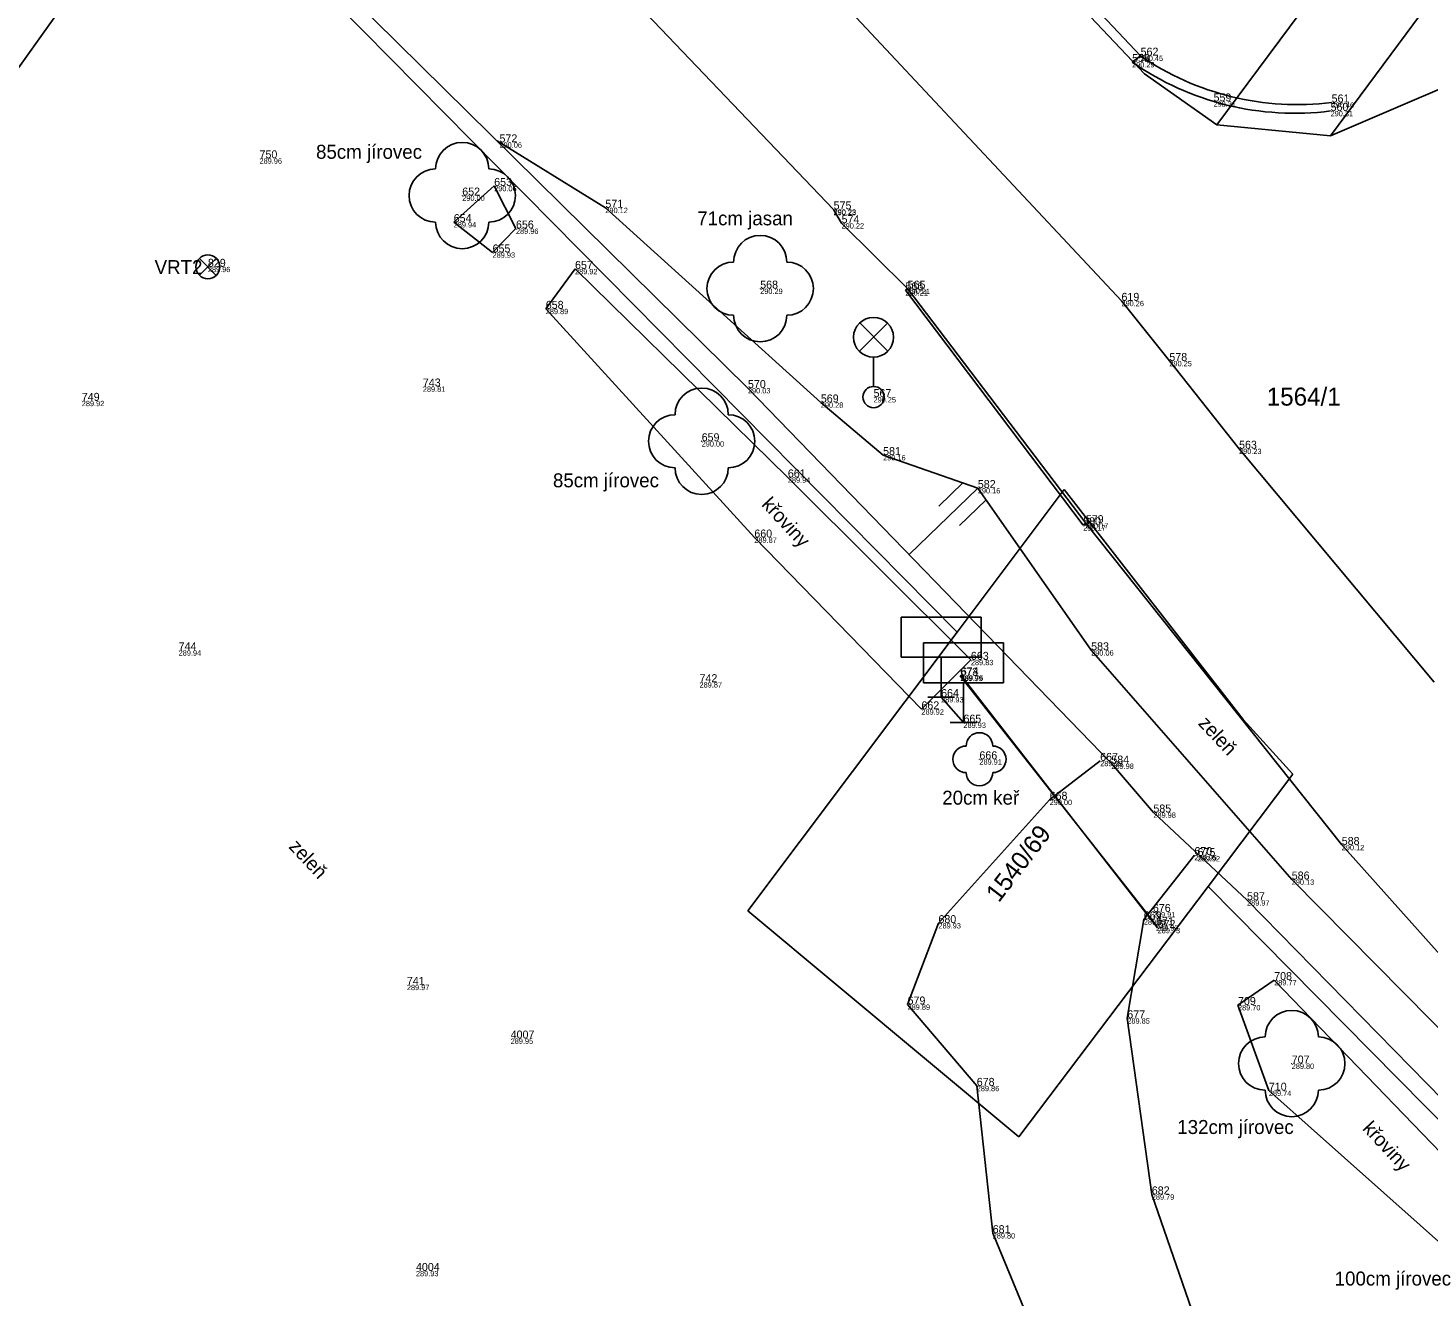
# Model space of a CAD drawing. Extents: x -805057 to -804930, y -994399 to -994240.
# Drawn here: x -805005.92 to -804979.61, y -994307.89 to -994284.05 of the extents above; entities that cross this region are included whole.
import ezdxf

# ---------------------------------------------------------------- set-up
doc = ezdxf.new("R2010")
doc.units = 0
for name, color, linetype in [('bod cislo', 7, 'Continuous'), ('bod pozice', 7, 'Continuous'), ('bod výška', 7, 'Continuous'), ('Katastralni mapa', 7, 'Continuous'), ('komunikace', 7, 'Continuous'), ('lampa', 7, 'Continuous'), ('plot', 7, 'Continuous'), ('podlaha', 7, 'Continuous'), ('popis', 7, 'Continuous'), ('strom', 7, 'Continuous'), ('svah', 7, 'Continuous'), ('trubka', 7, 'Continuous'), ('značka', 7, 'Continuous'), ('šrafy', 7, 'Continuous')]:
    doc.layers.add(name, color=color, linetype=linetype)

msp = doc.modelspace()

# ---------------------------------------------------------------- linework, layer by layer
at = {"layer": 'bod pozice'}
for p, q in [((-804985.01, -994284.57), (-804985.01, -994284.57)), ((-804985.17, -994284.69), (-804985.17, -994284.69)), ((-804983.64, -994285.43), (-804983.64, -994285.43)), ((-804981.44, -994285.61), (-804981.44, -994285.61)), ((-804981.42, -994285.45), (-804981.42, -994285.45)), ((-804997.06, -994286.2), (-804997.06, -994286.2)), ((-805001.57, -994286.5), (-805001.57, -994286.5)), ((-804997.76, -994287.2), (-804997.76, -994287.2)), ((-804997.16, -994287.02), (-804997.16, -994287.02)), ((-804995.07, -994287.43), (-804995.07, -994287.43)), ((-804990.78, -994287.46), (-804990.78, -994287.46)), ((-804997.92, -994287.7), (-804997.92, -994287.7)), ((-804990.63, -994287.72), (-804990.63, -994287.72)), ((-804996.75, -994287.82), (-804996.75, -994287.82)), ((-804997.19, -994288.27), (-804997.19, -994288.27)), ((-805002.54, -994288.54), (-805002.54, -994288.54)), ((-804995.64, -994288.58), (-804995.64, -994288.58)), ((-804992.16, -994288.95), (-804992.16, -994288.95)), ((-804989.43, -994288.98), (-804989.43, -994288.98)), ((-804989.39, -994288.95), (-804989.39, -994288.95)), ((-804985.37, -994289.18), (-804985.37, -994289.18)), ((-804996.19, -994289.33), (-804996.19, -994289.33)), ((-804984.47, -994290.31), (-804984.47, -994290.31)), ((-804998.5, -994290.79), (-804998.5, -994290.79)), ((-804992.39, -994290.82), (-804992.39, -994290.82)), ((-805004.91, -994291.06), (-805004.91, -994291.06)), ((-804991.02, -994291.09), (-804991.02, -994291.09)), ((-804990.03, -994290.99), (-804990.03, -994290.99)), ((-804993.26, -994291.82), (-804993.26, -994291.82)), ((-804989.85, -994292.08), (-804989.85, -994292.08)), ((-804983.16, -994291.96), (-804983.16, -994291.96)), ((-804991.64, -994292.5), (-804991.64, -994292.5)), ((-804988.07, -994292.7), (-804988.07, -994292.7)), ((-804986.09, -994293.4), (-804986.09, -994293.4)), ((-804986.04, -994293.36), (-804986.04, -994293.36)), ((-804992.27, -994293.63), (-804992.27, -994293.63)), ((-805003.09, -994295.75), (-805003.09, -994295.75)), ((-804985.94, -994295.75), (-804985.94, -994295.75)), ((-804988.2, -994295.93), (-804988.2, -994295.93)), ((-804993.3, -994296.35), (-804993.3, -994296.35)), ((-804988.4, -994296.23), (-804988.4, -994296.23)), ((-804988.39, -994296.22), (-804988.39, -994296.22)), ((-804988.76, -994296.63), (-804988.76, -994296.63)), ((-804989.13, -994296.86), (-804989.13, -994296.86)), ((-804988.34, -994297.11), (-804988.34, -994297.11)), ((-804988.04, -994297.8), (-804988.04, -994297.8)), ((-804985.77, -994297.83), (-804985.77, -994297.83)), ((-804985.56, -994297.88), (-804985.56, -994297.88)), ((-804986.72, -994298.56), (-804986.72, -994298.56)), ((-804984.77, -994298.8), (-804984.77, -994298.8)), ((-804981.23, -994299.41), (-804981.23, -994299.41)), ((-804984, -994299.6), (-804984, -994299.6)), ((-804983.94, -994299.62), (-804983.94, -994299.62)), ((-804982.17, -994300.06), (-804982.17, -994300.06)), ((-804983.01, -994300.45), (-804983.01, -994300.45)), ((-804988.81, -994300.88), (-804988.81, -994300.88)), ((-804984.95, -994300.81), (-804984.95, -994300.81)), ((-804984.78, -994300.67), (-804984.78, -994300.67)), ((-804984.72, -994300.92), (-804984.72, -994300.92)), ((-804984.69, -994300.97), (-804984.69, -994300.97)), ((-804982.5, -994301.95), (-804982.5, -994301.95)), ((-804998.8, -994302.04), (-804998.8, -994302.04)), ((-804989.39, -994302.41), (-804989.39, -994302.41)), ((-804983.18, -994302.42), (-804983.18, -994302.42)), ((-804985.26, -994302.67), (-804985.26, -994302.67)), ((-804996.85, -994303.05), (-804996.85, -994303.05)), ((-804982.17, -994303.52), (-804982.17, -994303.52)), ((-804988.09, -994303.94), (-804988.09, -994303.94)), ((-804982.6, -994304.03), (-804982.6, -994304.03)), ((-804984.8, -994305.98), (-804984.8, -994305.98)), ((-804987.79, -994306.71), (-804987.79, -994306.71)), ((-804998.63, -994307.42), (-804998.63, -994307.42))]:
    msp.add_line(p, q, dxfattribs=at)
at = {"layer": 'Katastralni mapa'}
for points in [[(-804981.44, -994286.08), (-804950.9, -994244.881)], [(-804963.36, -994258.68), (-804983.58, -994285.87)], [(-805017.39, -994266.11), (-804988.46, -994295.41)], [(-804989.57, -994280.01), (-804984.94, -994284.91), (-804983.58, -994285.87)], [(-804981.44, -994286.08), (-804977.99, -994284.6), (-804975.09, -994288.91)], [(-804983.58, -994285.87), (-804981.44, -994286.08)], [(-804986.45, -994292.73), (-804988.46, -994295.41)], [(-804986.45, -994292.73), (-804983.08, -994297.05), (-804982.15, -994298.08)], [(-804988.46, -994295.41), (-804992.39, -994300.65)], [(-804982.15, -994298.08), (-804983.74, -994300.19)], [(-804983.74, -994300.19), (-804987.3, -994304.9)], [(-804953.13, -994331.19), (-804983.74, -994300.19)], [(-804992.39, -994300.65), (-804987.3, -994304.9)]]:
    msp.add_lwpolyline(points, dxfattribs=at)
at = {"layer": 'komunikace'}
for p, q in [((-804985.37, -994289.18), (-805005.75, -994267.39)), ((-804989.14, -994280.19), (-804985.01, -994284.57)), ((-804985.01, -994284.57), (-804985.17, -994284.69)), ((-804989.39, -994288.95), (-804990.63, -994287.72)), ((-804989.39, -994288.95), (-804989.43, -994288.98)), ((-804986.09, -994293.4), (-804989.43, -994288.98)), ((-804986.04, -994293.36), (-804989.39, -994288.95)), ((-804984.47, -994290.31), (-804985.37, -994289.18)), ((-804983.16, -994291.96), (-804984.47, -994290.31)), ((-804979.49, -994296.35), (-804983.16, -994291.96)), ((-804986.04, -994293.36), (-804986.09, -994293.4)), ((-804981.23, -994299.41), (-804986.04, -994293.36)), ((-804986.72, -994298.56), (-804985.77, -994297.83)), ((-804988.81, -994300.88), (-804986.72, -994298.56)), ((-804974.7, -994306.71), (-804981.23, -994299.41)), ((-804984.95, -994300.81), (-804984, -994299.6)), ((-804989.39, -994302.41), (-804988.81, -994300.88)), ((-804984.95, -994300.81), (-804985.26, -994302.67)), ((-804988.09, -994303.94), (-804989.39, -994302.41)), ((-804985.26, -994302.67), (-804984.8, -994305.98)), ((-804987.79, -994306.71), (-804988.09, -994303.94)), ((-804980.44, -994318.62), (-804984.8, -994305.98)), ((-804987.79, -994306.71), (-804983.08, -994318.08))]:
    msp.add_line(p, q, dxfattribs=at)
msp.add_lwpolyline([(-804990.63, -994287.72), (-804990.78, -994287.46), (-804995.24, -994282.79)], dxfattribs=at)
for centre, major_axis, ratio, start_param, end_param in [((-804982.063, -994280.277), (1.576, -4.969), 0.99965, 5.374004, 6.10027), ((-804982.115, -994280.33), (5.308, -0.434), 0.999468, 4.183086, 4.921153)]:
    msp.add_ellipse(centre, major_axis=major_axis, ratio=ratio, start_param=start_param, end_param=end_param, dxfattribs=at)
at = {"layer": 'lampa'}
for p, q in [((-804990.294, -994290.128), (-804989.766, -994289.6)), ((-804990.294, -994290.128), (-804989.766, -994289.6)), ((-804989.758, -994290.125), (-804990.286, -994289.596)), ((-804989.758, -994290.125), (-804990.286, -994289.596)), ((-804990.03, -994290.79), (-804990.03, -994290.24)), ((-804990.03, -994290.79), (-804990.03, -994290.24))]:
    msp.add_line(p, q, dxfattribs=at)
for centre, radius in [((-804990.03, -994289.865), 0.375), ((-804990.03, -994289.865), 0.375), ((-804990.03, -994290.99), 0.2), ((-804990.03, -994290.99), 0.2)]:
    msp.add_circle(centre, radius, dxfattribs=at)
at = {"layer": 'plot'}
for p, q in [((-805002.96, -994280.4), (-805015.07, -994297.35)), ((-804992.39, -994290.82), (-805002.96, -994280.4)), ((-804985.56, -994297.88), (-804992.39, -994290.82)), ((-804985.56, -994297.88), (-804984.77, -994298.8)), ((-804983.01, -994300.45), (-804984.77, -994298.8)), ((-804972.34, -994311.34), (-804983.01, -994300.45))]:
    msp.add_line(p, q, dxfattribs=at)
at = {"layer": 'podlaha'}
for p, q in [((-805002.699, -994288.698), (-805002.382, -994288.382)), ((-805002.382, -994288.701), (-805002.699, -994288.382))]:
    msp.add_line(p, q, dxfattribs=at)
msp.add_circle((-805002.54, -994288.54), 0.225, dxfattribs=at)
at = {"layer": 'strom'}
for p, q in [((-804997.92, -994287.7), (-804997.16, -994287.02)), ((-804996.75, -994287.82), (-804997.16, -994287.02)), ((-804997.19, -994288.27), (-804997.92, -994287.7)), ((-804997.19, -994288.27), (-804996.75, -994287.82)), ((-804995.64, -994288.58), (-804996.19, -994289.33)), ((-804991.64, -994292.5), (-804995.64, -994288.58)), ((-804996.19, -994289.33), (-804992.27, -994293.63)), ((-804988.2, -994295.93), (-804991.64, -994292.5)), ((-804992.27, -994293.63), (-804989.13, -994296.86)), ((-804989.13, -994296.86), (-804988.2, -994295.93)), ((-804983.18, -994302.42), (-804982.5, -994301.95)), ((-804982.5, -994301.95), (-804978.12, -994306.5)), ((-804982.6, -994304.03), (-804983.18, -994302.42)), ((-804978.94, -994307.29), (-804982.6, -994304.03))]:
    msp.add_line(p, q, dxfattribs=at)
for centre, radius in [((-804997.76, -994287.2), 0.0005), ((-804992.16, -994288.95), 0.0005), ((-804993.26, -994291.82), 0.0005), ((-804988.04, -994297.8), 0.00025), ((-804982.17, -994303.52), 0.0005)]:
    msp.add_circle(centre, radius, dxfattribs=at)
for centre, radius, start, end in [((-804997.76, -994286.7), 0.5, 0, 180), ((-804998.26, -994287.2), 0.5, 90, 270), ((-804997.26, -994287.2), 0.5, 270, 90), ((-804997.76, -994287.7), 0.5, 180, 360), ((-804992.16, -994288.45), 0.5, 0, 180), ((-804992.66, -994288.95), 0.5, 90, 270), ((-804991.66, -994288.95), 0.5, 270, 90), ((-804992.16, -994289.45), 0.5, 180, 360), ((-804993.26, -994291.32), 0.5, 0, 180), ((-804993.76, -994291.82), 0.5, 90, 270), ((-804992.76, -994291.82), 0.5, 270, 90), ((-804993.26, -994292.32), 0.5, 180, 360), ((-804988.04, -994297.55), 0.25, 0, 180), ((-804988.29, -994297.8), 0.25, 90, 270), ((-804987.79, -994297.8), 0.25, 270, 90), ((-804988.04, -994298.05), 0.25, 180, 360), ((-804982.17, -994303.02), 0.5, 0, 180), ((-804982.67, -994303.52), 0.5, 90, 270), ((-804981.67, -994303.52), 0.5, 270, 90), ((-804982.17, -994304.02), 0.5, 180, 360)]:
    msp.add_arc(centre, radius, start, end, dxfattribs=at)
at = {"layer": 'svah'}
for p, q in [((-804995.07, -994287.43), (-804997.104, -994286.173)), ((-804991.02, -994291.09), (-804995.07, -994287.43)), ((-804989.85, -994292.08), (-804991.02, -994291.09)), ((-804988.07, -994292.7), (-804989.85, -994292.08)), ((-804985.94, -994295.75), (-804988.07, -994292.7)), ((-804982.17, -994300.06), (-804985.94, -994295.75)), ((-804971.58, -994310.78), (-804982.17, -994300.06))]:
    msp.add_line(p, q, dxfattribs=at)
at = {"layer": 'trubka'}
for p, q in [((-804988.4, -994296.23), (-804988.39, -994296.22)), ((-804984.72, -994300.92), (-804988.4, -994296.23)), ((-804988.39, -994296.22), (-804984.69, -994300.97)), ((-804984.69, -994300.97), (-804984.72, -994300.92))]:
    msp.add_line(p, q, dxfattribs=at)
at = {"layer": 'značka'}
for p, q in [((-804988.76, -994295.88), (-804988.76, -994296.63)), ((-804988.34, -994296.36), (-804988.34, -994297.11)), ((-804989.01, -994296.63), (-804988.51, -994296.63)), ((-804988.34, -994297.11), (-804988.76, -994296.63)), ((-804988.59, -994297.11), (-804988.09, -994297.11))]:
    msp.add_line(p, q, dxfattribs=at)
for points in [[(-804989.51, -994295.88), (-804988.01, -994295.88), (-804988.01, -994295.13), (-804989.51, -994295.13)], [(-804989.09, -994296.36), (-804987.59, -994296.36), (-804987.59, -994295.61), (-804989.09, -994295.61)]]:
    msp.add_lwpolyline(points, close=True, dxfattribs=at)
at = {"layer": 'šrafy'}
for p, q in [((-804988.07, -994292.7), (-804989.36, -994293.952)), ((-804988.351, -994292.602), (-804988.802, -994293.039)), ((-804987.915, -994292.922), (-804988.413, -994293.405))]:
    msp.add_line(p, q, dxfattribs=at)

# ---------------------------------------------------------------- texts
at = {"layer": 'bod cislo'}
for s, p in [('558    ', (-804985.17, -994284.69)), ('562    ', (-804985.01, -994284.57)), ('559    ', (-804983.64, -994285.43)), ('561    ', (-804981.42, -994285.45)), ('560    ', (-804981.44, -994285.61)), ('572    ', (-804997.06, -994286.2)), ('750    ', (-805001.57, -994286.5)), ('653    ', (-804997.16, -994287.02)), ('652    ', (-804997.76, -994287.2)), ('571    ', (-804995.07, -994287.43)), ('575    ', (-804990.78, -994287.46)), ('654    ', (-804997.92, -994287.7)), ('656    ', (-804996.75, -994287.82)), ('574    ', (-804990.63, -994287.72)), ('655    ', (-804997.19, -994288.27)), ('829    ', (-805002.54, -994288.54)), ('657    ', (-804995.64, -994288.58)), ('568    ', (-804992.16, -994288.95)), ('566    ', (-804989.43, -994288.98)), ('565    ', (-804989.39, -994288.95)), ('619    ', (-804985.37, -994289.18)), ('658    ', (-804996.19, -994289.33)), ('578    ', (-804984.47, -994290.31)), ('743    ', (-804998.5, -994290.79)), ('570    ', (-804992.39, -994290.82)), ('567    ', (-804990.03, -994290.99)), ('749    ', (-805004.91, -994291.06)), ('569    ', (-804991.02, -994291.09)), ('659    ', (-804993.26, -994291.82)), ('581    ', (-804989.85, -994292.08)), ('563    ', (-804983.16, -994291.96)), ('661    ', (-804991.64, -994292.5)), ('582    ', (-804988.07, -994292.7)), ('580    ', (-804986.09, -994293.4)), ('579    ', (-804986.04, -994293.36)), ('660    ', (-804992.27, -994293.63)), ('744    ', (-805003.09, -994295.75)), ('583    ', (-804985.94, -994295.75)), ('663    ', (-804988.2, -994295.93)), ('673    ', (-804988.4, -994296.23)), ('674    ', (-804988.39, -994296.22)), ('742    ', (-804993.3, -994296.35)), ('664    ', (-804988.76, -994296.63)), ('662    ', (-804989.13, -994296.86)), ('665    ', (-804988.34, -994297.11)), ('666    ', (-804988.04, -994297.8)), ('667    ', (-804985.77, -994297.83)), ('584    ', (-804985.56, -994297.88)), ('668    ', (-804986.72, -994298.56)), ('585    ', (-804984.77, -994298.8)), ('588    ', (-804981.23, -994299.41)), ('670    ', (-804984, -994299.6)), ('675    ', (-804983.94, -994299.62)), ('586    ', (-804982.17, -994300.06)), ('587    ', (-804983.01, -994300.45)), ('676    ', (-804984.78, -994300.67)), ('680    ', (-804988.81, -994300.88)), ('669    ', (-804984.95, -994300.81)), ('671    ', (-804984.72, -994300.92)), ('672    ', (-804984.69, -994300.97)), ('741    ', (-804998.8, -994302.04)), ('708    ', (-804982.5, -994301.95)), ('679    ', (-804989.39, -994302.41)), ('709    ', (-804983.18, -994302.42)), ('677    ', (-804985.26, -994302.67)), ('4007    ', (-804996.85, -994303.05)), ('707    ', (-804982.17, -994303.52)), ('678    ', (-804988.09, -994303.94)), ('710    ', (-804982.6, -994304.03)), ('682    ', (-804984.8, -994305.98)), ('681    ', (-804987.79, -994306.71)), ('4004    ', (-804998.63, -994307.42))]:
    msp.add_text(s, height=0.15, dxfattribs=at).set_placement(p)
at = {"layer": 'bod výška'}
for s, p in [('290.45  ', (-804985.01, -994284.67)), ('290.29  ', (-804985.17, -994284.79)), ('290.31  ', (-804983.64, -994285.53)), ('290.31  ', (-804981.44, -994285.71)), ('290.46  ', (-804981.42, -994285.55)), ('290.06  ', (-804997.06, -994286.3)), ('289.96  ', (-805001.57, -994286.6)), ('290.00  ', (-804997.76, -994287.3)), ('290.06  ', (-804997.16, -994287.12)), ('290.12  ', (-804995.07, -994287.53)), ('290.23  ', (-804990.78, -994287.56)), ('290.23  ', (-804990.78, -994287.57)), ('289.94  ', (-804997.92, -994287.8)), ('290.22  ', (-804990.63, -994287.82)), ('289.96  ', (-804996.75, -994287.92)), ('289.93  ', (-804997.19, -994288.37)), ('289.96  ', (-805002.54, -994288.64)), ('289.92  ', (-804995.64, -994288.68)), ('290.29  ', (-804992.16, -994289.05)), ('290.21  ', (-804989.43, -994289.08)), ('290.21  ', (-804989.39, -994289.05)), ('290.26  ', (-804985.37, -994289.28)), ('289.89  ', (-804996.19, -994289.43)), ('290.25  ', (-804984.47, -994290.41)), ('289.81  ', (-804998.5, -994290.89)), ('290.03  ', (-804992.39, -994290.92)), ('289.92  ', (-805004.91, -994291.16)), ('290.28  ', (-804991.02, -994291.19)), ('290.25  ', (-804990.03, -994291.09)), ('290.00  ', (-804993.26, -994291.92)), ('290.16  ', (-804989.85, -994292.18)), ('290.23  ', (-804983.16, -994292.06)), ('289.94  ', (-804991.64, -994292.6)), ('290.16  ', (-804988.07, -994292.8)), ('290.17  ', (-804986.09, -994293.5)), ('290.17  ', (-804986.04, -994293.46)), ('289.87  ', (-804992.27, -994293.73)), ('289.94  ', (-805003.09, -994295.85)), ('290.06  ', (-804985.94, -994295.85)), ('289.83  ', (-804988.2, -994296.03)), ('289.87  ', (-804993.3, -994296.45)), ('289.99  ', (-804988.4, -994296.33)), ('289.76  ', (-804988.39, -994296.32)), ('289.93  ', (-804988.76, -994296.73)), ('289.92  ', (-804989.13, -994296.96)), ('289.93  ', (-804988.34, -994297.21)), ('289.91  ', (-804988.04, -994297.9)), ('289.99  ', (-804985.77, -994297.93)), ('289.98  ', (-804985.56, -994297.98)), ('290.00  ', (-804986.72, -994298.66)), ('289.98  ', (-804984.77, -994298.9)), ('290.12  ', (-804981.23, -994299.51)), ('289.95  ', (-804984, -994299.7)), ('289.92  ', (-804983.94, -994299.72)), ('290.13  ', (-804982.17, -994300.16)), ('289.97  ', (-804983.01, -994300.55)), ('289.93  ', (-804988.81, -994300.98)), ('289.95  ', (-804984.95, -994300.91)), ('289.91  ', (-804984.78, -994300.77)), ('289.93  ', (-804984.72, -994301.02)), ('289.73  ', (-804984.69, -994301.07)), ('289.77  ', (-804982.5, -994302.05)), ('289.97  ', (-804998.8, -994302.14)), ('289.89  ', (-804989.39, -994302.51)), ('289.70  ', (-804983.18, -994302.52)), ('289.85  ', (-804985.26, -994302.77)), ('289.95', (-804996.85, -994303.15)), ('289.80  ', (-804982.17, -994303.62)), ('289.86  ', (-804988.09, -994304.04)), ('289.74  ', (-804982.6, -994304.13)), ('289.79  ', (-804984.8, -994306.08)), ('289.80  ', (-804987.79, -994306.81)), ('289.93  ', (-804998.63, -994307.52))]:
    msp.add_text(s, height=0.1, dxfattribs=at).set_placement(p)
at = {"layer": 'Katastralni mapa'}
msp.add_text('1564/1', height=0.34, dxfattribs=at).set_placement((-804982.64, -994291.15))
msp.add_text('1540/69', height=0.34, rotation=52.5004, dxfattribs=at).set_placement((-804987.676, -994300.508))
at = {"layer": 'popis'}
for s, height, p in [('85cm jírovec', 0.26289, (-805000.508, -994286.509)), ('71cm jasan', 0.2629, (-804993.343, -994287.76)), ('VRT2', 0.2629, (-805003.541, -994288.677)), ('85cm jírovec', 0.26289, (-804996.055, -994292.686)), ('20cm keř', 0.2629, (-804988.738, -994298.653)), ('132cm jírovec', 0.26289, (-804984.321, -994304.845)), ('100cm jírovec', 0.26289, (-804981.363, -994307.694))]:
    msp.add_text(s, height=height, dxfattribs=at).set_placement(p)
for s, rotation, p in [('křoviny', 312.8096, (-804992.149, -994293.021)), ('zeleň', 313.0307, (-804983.942, -994297.136)), ('zeleň', 313.0307, (-805001.035, -994299.454)), ('křoviny', 312.8096, (-804980.854, -994304.753))]:
    msp.add_text(s, height=0.2629, rotation=rotation, dxfattribs=at).set_placement(p)

doc.saveas('drawing.dxf')
